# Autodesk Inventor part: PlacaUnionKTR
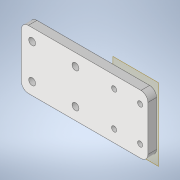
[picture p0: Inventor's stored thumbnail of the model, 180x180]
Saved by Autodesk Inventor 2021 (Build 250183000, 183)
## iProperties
Created: 2021-02
Part Number: PlacaUnionKTR
Material: Genérico
Document SubType Name: Modeling
Designer: ATOUZA
Density: 1 g/cm^3
Appearance: Valor por defecto
Author: ATOUZA
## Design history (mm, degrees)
node "Plano de trabajo1"
sketch "Boceto1"
  geometry: L1 (-24, 0)-(0, 0) reference; L2 (-24, 0)-(-24, -38) reference; L3 (0, -38)-(-24, -38) reference; L4 (-45.275, 1.9)-(-48.575, 1.9) reference; L5 (-48.575, 1.9)-(-48.575, -56.5) reference; L6 (-45.275, -56.5)-(-48.575, -56.5) reference; L7 (-45.275, 1.9)-(-45.275, -56.5) reference; L8 (-59.975, 1.9)-(-63.275, 1.9) reference; L9 (-63.275, 1.9)-(-63.275, -56.5) reference; L10 (-59.975, -56.5)-(-63.275, -56.5) reference; L11 (-59.975, 1.9)-(-59.975, -56.5) reference; L12 (-48.575, 1.9)-(-59.975, 1.9) reference; L13 (-59.975, 1.9)-(-59.975, -56.5) reference; L14 (-48.575, -56.5)-(-59.975, -56.5) reference; L15 (-48.575, 1.9)-(-48.575, -56.5) reference; L16 (-63.275, -41)-(-45.275, -41) reference; L17 (0, -2)-(-73, -2); L18 (-73, -2)-(-73, -36); L19 (-73, -36)-(0, -36); L20 (0, -2)-(0, -36); L21 (-54.275, 1.9)-(-54.275, -36); L22 (-54.275, -9)-(-41.775, -9); L23 (-54.275, -19)-(-45.275, -19); C1 r 1.5 at (-4.5, -29) reference; C2 r 1.5 at (-4.5, -9) reference; C3 r 1.5 at (-19.5, -29) reference; C4 r 1.5 at (-19.5, -9) reference; C5 r 1.5 at (-19.5, -9); C6 r 1.5 at (-4.5, -9); C7 r 1.5 at (-19.5, -29); C8 r 1.5 at (-4.5, -29); C9 r 2 at (-41.775, -9); C10 r 2 at (-66.775, -9); C11 r 2 at (-41.775, -29); C12 r 2 at (-66.775, -29)
  constraints: 14 end point, 8 centre point, 5 coincident, 4 concentric, 4 perpendicular, 4 point on line, 3 symmetric about line, 1 horizontal, 1 midpoint, 1 parallel, 1 vertical, 3 other
  dimensions: "d0" = 12.5 distance of L22.start L22.end; "d1" = 4 diameter of C9; "d2" = 34 distance of L17.end L18.end; "d3" = 73 distance of L18.end L19.end; "d4" = 73 distance from line of L18 L1.end; "d5" = 7 distance from line of L17 C4.centre; "d6" = 7 distance from line of L19 C3.centre (derived); "d7" = 20 distance of C3.centre C4.centre (derived); "d8" = 7 distance from line of L17 L22.end; "d9" = 20 distance of C11.centre C9.centre
extrude "Extrusión1" new body sketch "Boceto1" distance "d10" = 5; taper "d11" = 0 deg
fillet "Empalme1" dims "d12" = 4
node "Sólido1"
node "Referencia2"
node "Referencia3"
node "Referencia4"
node "Referencia5"
